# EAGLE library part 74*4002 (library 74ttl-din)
Dual 4-input NOR
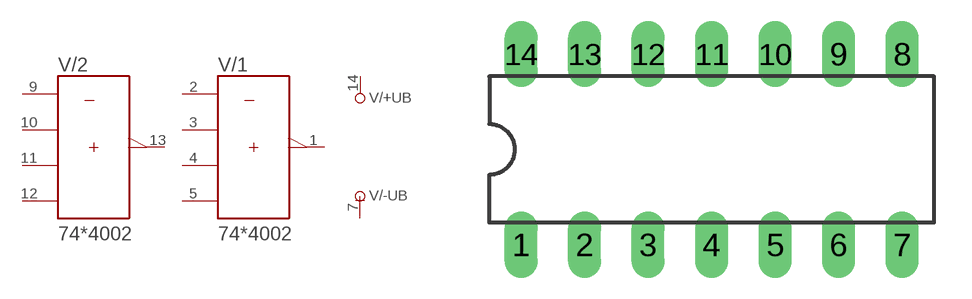
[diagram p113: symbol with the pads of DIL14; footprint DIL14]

Designator prefix V; gates /+UB=+UB /-UB=-UB /1=4002 /2=4002

## 744002N  [DIL14]
1  /1:Y  out
2  /1:A  in
3  /1:B  in
4  /1:C  in
5  /1:D  in
7  /-UB:-UB  pwr
9  /2:A  in
10  /2:B  in
11  /2:C  in
12  /2:D  in
13  /2:Y  out
14  /+UB:+UB  pwr

## Footprint DIL14 (pad centres in mm)
Dual In Line Package
drill 0.813 long: 1 -7.62,-3.81; 2 -5.08,-3.81; 3 -2.54,-3.81; 4 0,-3.81; 5 2.54,-3.81; 6 5.08,-3.81; 7 7.62,-3.81; 8 7.62,3.81; 9 5.08,3.81; 10 2.54,3.81; 11 0,3.81; 12 -2.54,3.81; 13 -5.08,3.81; 14 -7.62,3.81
